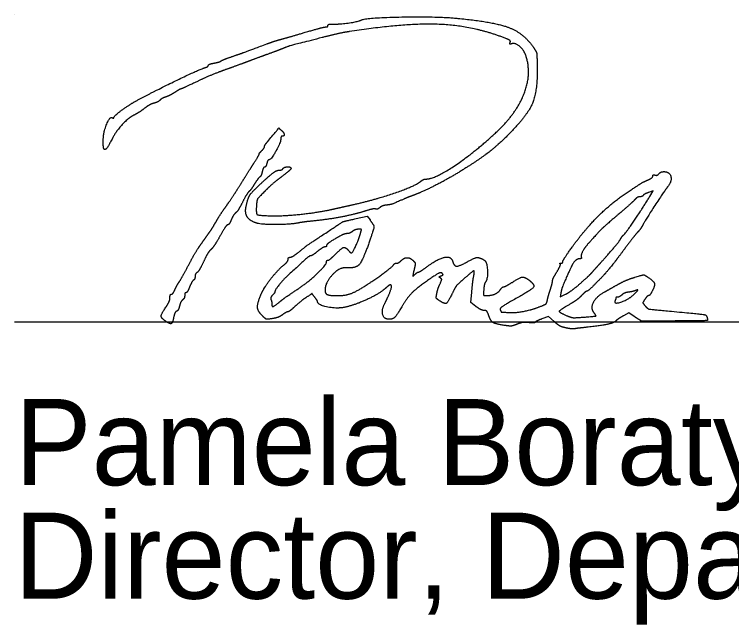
# Model space of a CAD drawing. Extents: x 0 to 34, y 0 to 22.
# Drawn here: x 24.528 to 25.693, y 4.24 to 5.232 of the extents above; entities that cross this region are included whole.
import ezdxf

# ---------------------------------------------------------------- set-up
doc = ezdxf.new("R2010")
doc.units = 0
for name, color, linetype in [('SH_Data', 7, 'Continuous'), ('SH_Text', 7, 'Continuous'), ('TX_P_1', 7, 'Continuous')]:
    doc.layers.add(name, color=color, linetype=linetype)

msp = doc.modelspace()

# ---------------------------------------------------------------- linework, layer by layer
at = {"layer": 'SH_Data'}
for p, q in [((24.5279, 5.2323), (24.5279, 5.2323)), ((24.5279, 4.7323), (28.0279, 4.7323))]:
    msp.add_line(p, q, dxfattribs=at)
at = {"layer": 'TX_P_1'}
for points in [[(25.5604, 4.9363), (25.5658, 4.9453), (25.5584, 4.9427)], [(25.0831, 4.9002), (25.1011, 4.9042), (25.1058, 4.898)], [(25.278, 4.7574), (25.2697, 4.7637), (25.2712, 4.7808)], [(25.416, 4.7793), (25.415, 4.7729), (25.4236, 4.7773)], [(25.5368, 4.74), (25.5262, 4.7468), (25.5178, 4.7423)], [(25.405, 4.733), (25.3958, 4.7413), (25.3852, 4.7372)]]:
    msp.add_lwpolyline(points, dxfattribs=at)
for points in [[(25.0465, 5.2165), (25.0561, 5.2162), (25.0871, 5.2206), (25.0905, 5.2227)], [(25.0905, 5.2227), (25.0973, 5.2269), (25.2143, 5.2292), (25.2487, 5.2258)], [(25.2487, 5.2258), (25.3079, 5.22), (25.3555, 5.2017), (25.3713, 5.1787)], [(25.0007, 5.2031), (25.0168, 5.2079), (25.0317, 5.2118), (25.0337, 5.2118)], [(25.0337, 5.2118), (25.0358, 5.2118), (25.0375, 5.2129), (25.0375, 5.2143)], [(25.0375, 5.2143), (25.0375, 5.2157), (25.0415, 5.2167), (25.0465, 5.2165)], [(25.3212, 5.1951), (25.2706, 5.2141), (25.1626, 5.2181), (25.0723, 5.2043)], [(24.9619, 5.192), (24.9672, 5.1934), (24.9846, 5.1984), (25.0007, 5.2031)], [(25.0723, 5.2043), (25.063, 5.2029), (25.0431, 5.1985), (25.0279, 5.1946)], [(24.9379, 5.1842), (24.9458, 5.1871), (24.9566, 5.1906), (24.9619, 5.192)], [(25.0279, 5.1946), (24.9769, 5.1814), (24.9726, 5.1802), (24.9619, 5.1758)], [(25.3335, 5.1865), (25.3345, 5.189), (25.331, 5.1914), (25.3212, 5.1951)], [(24.8815, 5.1636), (24.8962, 5.1687), (24.9027, 5.171), (24.9379, 5.1842)], [(24.9619, 5.1758), (24.9592, 5.1747), (24.949, 5.1709), (24.9391, 5.1673)], [(25.3359, 5.1844), (25.3333, 5.1834), (25.3326, 5.184), (25.3335, 5.1865)], [(25.3593, 5.1645), (25.356, 5.1742), (25.3416, 5.1866), (25.3359, 5.1844)], [(25.3713, 5.1787), (25.3762, 5.1714), (25.3771, 5.1671), (25.3775, 5.1492)], [(24.8635, 5.1564), (24.8648, 5.1574), (24.8729, 5.1606), (24.8815, 5.1636)], [(24.9391, 5.1673), (24.9292, 5.1637), (24.9141, 5.1582), (24.9055, 5.1549)], [(25.3138, 5.0433), (25.3447, 5.0727), (25.3686, 5.1362), (25.3593, 5.1645)], [(24.8431, 5.1493), (24.8431, 5.1504), (24.8471, 5.152), (24.8521, 5.153)], [(24.8521, 5.153), (24.857, 5.1539), (24.8622, 5.1554), (24.8635, 5.1564)], [(24.9055, 5.1549), (24.8969, 5.1517), (24.8807, 5.1458), (24.8695, 5.1418)], [(24.7255, 5.0914), (24.7557, 5.1077), (24.8293, 5.1433), (24.8377, 5.1457)], [(24.8695, 5.1418), (24.8583, 5.1378), (24.8379, 5.1293), (24.8243, 5.1228)], [(24.8377, 5.1457), (24.8407, 5.1466), (24.8431, 5.1482), (24.8431, 5.1493)], [(25.3775, 5.1492), (25.3782, 5.1084), (25.3621, 5.0687), (25.3327, 5.0388)], [(24.8243, 5.1228), (24.8106, 5.1163), (24.799, 5.111), (24.7984, 5.111)], [(24.7884, 5.1054), (24.7835, 5.1022), (24.7768, 5.0989), (24.7736, 5.0978)], [(24.7984, 5.111), (24.7978, 5.111), (24.7934, 5.1085), (24.7884, 5.1054)], [(24.7736, 5.0978), (24.7704, 5.0968), (24.7662, 5.0945), (24.7644, 5.0927)], [(24.6895, 5.0648), (24.6895, 5.0669), (24.7149, 5.0857), (24.7255, 5.0914)], [(24.7547, 5.0879), (24.7512, 5.087), (24.7445, 5.0834), (24.7399, 5.0798)], [(24.7644, 5.0927), (24.7626, 5.0909), (24.7583, 5.0887), (24.7547, 5.0879)], [(24.7399, 5.0798), (24.7353, 5.0762), (24.7281, 5.0715), (24.724, 5.0694)], [(24.6723, 5.0269), (24.6724, 5.0401), (24.683, 5.0667), (24.6872, 5.0641)], [(24.6872, 5.0641), (24.6885, 5.0634), (24.6895, 5.0637), (24.6895, 5.0648)], [(24.724, 5.0694), (24.7136, 5.0641), (24.6937, 5.0432), (24.6875, 5.0311)], [(24.9397, 5.0258), (24.9582, 5.048), (24.9575, 5.0474), (24.9616, 5.044)], [(24.9616, 5.044), (24.9659, 5.0405), (24.9668, 5.0342), (24.9631, 5.0342)], [(25.1971, 4.9646), (25.2112, 4.9646), (25.2793, 5.0105), (25.3138, 5.0433)], [(25.3327, 5.0388), (25.3141, 5.0199), (25.2817, 4.995), (25.2512, 4.9762)], [(24.6737, 5.0132), (24.6729, 5.014), (24.6723, 5.0202), (24.6723, 5.0269)], [(24.6875, 5.0311), (24.6808, 5.0182), (24.6755, 5.0114), (24.6737, 5.0132)], [(24.9343, 5.0172), (24.9343, 5.0184), (24.9367, 5.0223), (24.9397, 5.0258)], [(24.9607, 5.0291), (24.9607, 5.0236), (24.9448, 4.9958), (24.9416, 4.9958)], [(24.9631, 5.0342), (24.9618, 5.0342), (24.9607, 5.0319), (24.9607, 5.0291)], [(24.9295, 5.0102), (24.9321, 5.0128), (24.9343, 5.016), (24.9343, 5.0172)], [(24.9167, 4.9897), (24.9223, 4.9984), (24.9263, 5.0054), (24.9257, 5.0054)], [(24.9257, 5.0054), (24.9252, 5.0054), (24.9268, 5.0076), (24.9295, 5.0102)], [(24.8947, 4.9547), (24.9013, 4.9654), (24.9112, 4.9811), (24.9167, 4.9897)], [(24.9381, 4.9898), (24.9373, 4.9865), (24.9356, 4.9838), (24.9344, 4.9838)], [(24.9416, 4.9958), (24.9405, 4.9958), (24.9389, 4.9931), (24.9381, 4.9898)], [(24.9259, 4.9548), (24.9416, 4.9695), (24.9543, 4.979), (24.9583, 4.979)], [(24.9344, 4.9838), (24.9332, 4.9838), (24.9316, 4.9806), (24.9307, 4.9766)], [(24.9583, 4.979), (24.9608, 4.979), (24.9635, 4.9801), (24.9643, 4.9814)], [(24.9775, 4.9818), (24.9775, 4.9807), (24.9707, 4.9748), (24.9625, 4.9686)], [(24.9643, 4.9814), (24.9661, 4.9843), (24.9775, 4.9846), (24.9775, 4.9818)], [(24.9268, 4.968), (24.9255, 4.9672), (24.9217, 4.9621), (24.9183, 4.9566)], [(24.9307, 4.9766), (24.9298, 4.9727), (24.9281, 4.9688), (24.9268, 4.968)], [(24.9625, 4.9686), (24.9542, 4.9625), (24.9417, 4.9517), (24.9347, 4.9445)], [(25.2512, 4.9762), (25.232, 4.9644), (25.1908, 4.9434), (25.1767, 4.9383)], [(25.5577, 4.9632), (25.562, 4.9652), (25.5655, 4.968), (25.5655, 4.9695)], [(25.5655, 4.9695), (25.5655, 4.9711), (25.567, 4.9717), (25.5689, 4.971)], [(25.5689, 4.971), (25.5708, 4.9703), (25.5736, 4.9712), (25.5752, 4.9731)], [(25.5752, 4.9731), (25.5768, 4.975), (25.5805, 4.9766), (25.5834, 4.9766)], [(25.5834, 4.9766), (25.5928, 4.9766), (25.5966, 4.9606), (25.5892, 4.9516)], [(24.8729, 4.9218), (24.8783, 4.9293), (24.8881, 4.9441), (24.8947, 4.9547)], [(24.9045, 4.9202), (24.9073, 4.9333), (24.9134, 4.9432), (24.9259, 4.9548)], [(24.9183, 4.9566), (24.9149, 4.9511), (24.9108, 4.9455), (24.9091, 4.9442)], [(25.0771, 4.9227), (25.114, 4.9309), (25.1803, 4.9538), (25.1889, 4.9613)], [(25.1889, 4.9613), (25.191, 4.9631), (25.1946, 4.9646), (25.1971, 4.9646)], [(25.5287, 4.9462), (25.5476, 4.9585), (25.5495, 4.9596), (25.5577, 4.9632)], [(24.9091, 4.9442), (24.9075, 4.9428), (24.9028, 4.9352), (24.8988, 4.9272)], [(24.9347, 4.9445), (24.924, 4.9336), (24.9218, 4.9299), (24.9213, 4.9217)], [(25.4341, 4.8537), (25.4563, 4.8845), (25.5014, 4.9285), (25.5287, 4.9462)], [(25.5892, 4.9516), (25.585, 4.9466), (25.5522, 4.8961), (25.549, 4.8899)], [(25.5584, 4.9427), (25.5544, 4.9413), (25.5505, 4.9392), (25.5497, 4.938)], [(25.161, 4.9321), (25.144, 4.9246), (25.1391, 4.9229), (25.1325, 4.9222)], [(25.1767, 4.9383), (25.1721, 4.9366), (25.165, 4.9338), (25.161, 4.9321)], [(25.5356, 4.9304), (25.5329, 4.9274), (25.5204, 4.9164), (25.5079, 4.9058)], [(25.5176, 4.8734), (25.5204, 4.8754), (25.5486, 4.9169), (25.5604, 4.9363)], [(25.5444, 4.9358), (25.5422, 4.9358), (25.5382, 4.9334), (25.5356, 4.9304)], [(25.5497, 4.938), (25.549, 4.9368), (25.5466, 4.9358), (25.5444, 4.9358)], [(24.8562, 4.8962), (24.86, 4.9028), (24.8676, 4.9143), (24.8729, 4.9218)], [(24.8988, 4.9272), (24.8948, 4.9192), (24.8897, 4.9112), (24.8875, 4.9095)], [(24.9199, 4.8934), (24.9094, 4.8973), (24.9023, 4.9097), (24.9045, 4.9202)], [(24.9213, 4.9217), (24.9204, 4.9082), (24.9245, 4.9053), (24.9451, 4.9048)], [(25.0435, 4.9152), (25.0514, 4.917), (25.0665, 4.9203), (25.0771, 4.9227)], [(25.1325, 4.9222), (25.1286, 4.9217), (25.1237, 4.9199), (25.1217, 4.9181)], [(24.8875, 4.9095), (24.8854, 4.9077), (24.8821, 4.9026), (24.8803, 4.8982)], [(24.9451, 4.9048), (24.9643, 4.9043), (25.0222, 4.9104), (25.0435, 4.9152)], [(25.0969, 4.9122), (25.0804, 4.9069), (25.0353, 4.8984), (25.0115, 4.8961)], [(25.1149, 4.9159), (25.1132, 4.9165), (25.1051, 4.9148), (25.0969, 4.9122)], [(25.1217, 4.9181), (25.1196, 4.9163), (25.1165, 4.9153), (25.1149, 4.9159)], [(24.8432, 4.8756), (24.8465, 4.8803), (24.8524, 4.8896), (24.8562, 4.8962)], [(24.8803, 4.8982), (24.8784, 4.8938), (24.8759, 4.8902), (24.8746, 4.8902)], [(25.0115, 4.8961), (25.0032, 4.8953), (24.994, 4.8941), (24.9911, 4.8935)], [(25.0291, 4.8737), (25.0607, 4.8948), (25.0621, 4.8955), (25.0831, 4.9002)], [(25.1058, 4.898), (25.1124, 4.8893), (25.1122, 4.8844), (25.1045, 4.8619)], [(25.5079, 4.9058), (25.4883, 4.8893), (25.4766, 4.8779), (25.4599, 4.859)], [(24.8746, 4.8902), (24.8733, 4.8902), (24.8679, 4.8823), (24.8625, 4.8726)], [(24.9911, 4.8935), (24.9774, 4.8905), (24.9279, 4.8904), (24.9199, 4.8934)], [(25.549, 4.8899), (25.5473, 4.8865), (25.5434, 4.881), (25.5404, 4.8778)], [(24.8296, 4.8564), (24.8337, 4.8622), (24.8398, 4.8708), (24.8432, 4.8756)], [(24.8625, 4.8726), (24.8572, 4.863), (24.8505, 4.853), (24.8477, 4.8504)], [(24.9899, 4.8458), (25.0036, 4.8569), (25.0016, 4.8555), (25.0291, 4.8737)], [(25.0588, 4.8727), (25.0443, 4.8647), (25.0351, 4.8583), (25.0351, 4.8564)], [(25.0685, 4.8758), (25.0663, 4.8758), (25.0619, 4.8744), (25.0588, 4.8727)], [(25.0772, 4.8793), (25.0747, 4.8774), (25.0707, 4.8758), (25.0685, 4.8758)], [(25.0757, 4.8446), (25.0775, 4.8446), (25.0873, 4.8657), (25.0904, 4.8764)], [(25.0871, 4.8829), (25.0842, 4.8829), (25.0798, 4.8813), (25.0772, 4.8793)], [(25.0904, 4.8764), (25.0921, 4.8822), (25.0917, 4.883), (25.0871, 4.8829)], [(25.5137, 4.8683), (25.5149, 4.8704), (25.5167, 4.8727), (25.5176, 4.8734)], [(25.5404, 4.8778), (25.5374, 4.8746), (25.5285, 4.8632), (25.5206, 4.8526)], [(25.1045, 4.8619), (25.0942, 4.832), (25.0822, 4.8189), (25.0663, 4.8202)], [(25.4824, 4.8304), (25.4977, 4.8476), (25.5113, 4.8639), (25.5137, 4.8683)], [(24.8107, 4.8242), (24.817, 4.8361), (24.8255, 4.8506), (24.8296, 4.8564)], [(24.8477, 4.8504), (24.8448, 4.8479), (24.8393, 4.8388), (24.8354, 4.8302)], [(25.0324, 4.8542), (25.031, 4.8542), (25.0257, 4.851), (25.0207, 4.847)], [(25.0351, 4.8564), (25.0351, 4.8552), (25.0339, 4.8542), (25.0324, 4.8542)], [(25.0495, 4.8422), (25.0596, 4.8523), (25.0661, 4.8542), (25.0711, 4.8482)], [(25.4191, 4.8304), (25.4191, 4.8318), (25.4258, 4.8423), (25.4341, 4.8537)], [(25.4599, 4.859), (25.454, 4.8524), (25.4478, 4.8396), (25.4492, 4.8372)], [(25.5206, 4.8526), (25.5127, 4.8419), (25.505, 4.8317), (25.5036, 4.8299)], [(24.9727, 4.834), (24.9727, 4.8359), (24.9742, 4.8374), (24.9761, 4.8374)], [(25.0095, 4.8398), (25.0076, 4.8398), (24.9992, 4.8325), (24.9739, 4.8093)], [(24.9761, 4.8374), (24.9779, 4.8374), (24.9841, 4.8412), (24.9899, 4.8458)], [(25.0207, 4.847), (25.0157, 4.843), (25.0107, 4.8398), (25.0095, 4.8398)], [(25.0375, 4.8326), (25.0388, 4.8326), (25.0442, 4.8369), (25.0495, 4.8422)], [(25.0711, 4.8482), (25.0727, 4.8462), (25.0748, 4.8446), (25.0757, 4.8446)], [(25.1942, 4.8191), (25.2145, 4.8343), (25.2372, 4.8399), (25.2402, 4.8305)], [(25.264, 4.8301), (25.2759, 4.8367), (25.2832, 4.8374), (25.2914, 4.8328)], [(25.4492, 4.8372), (25.45, 4.836), (25.4489, 4.835), (25.4469, 4.835)], [(24.8354, 4.8302), (24.8314, 4.8216), (24.8267, 4.8137), (24.8249, 4.8127)], [(24.9292, 4.7779), (24.9337, 4.7884), (24.9569, 4.8178), (24.9673, 4.8262)], [(24.9673, 4.8262), (24.9702, 4.8286), (24.9727, 4.8321), (24.9727, 4.834)], [(24.989, 4.786), (25.0046, 4.7964), (25.0351, 4.8252), (25.0351, 4.8295)], [(25.0351, 4.8295), (25.0351, 4.8312), (25.0362, 4.8326), (25.0375, 4.8326)], [(25.1438, 4.8247), (25.1449, 4.8264), (25.1472, 4.8278), (25.149, 4.8278)], [(25.149, 4.8278), (25.1509, 4.8278), (25.1541, 4.8296), (25.1562, 4.8317)], [(25.1562, 4.8317), (25.1612, 4.8367), (25.1712, 4.8367), (25.1761, 4.8318)], [(25.1761, 4.8318), (25.1793, 4.8286), (25.1795, 4.8261), (25.1774, 4.817)], [(25.2402, 4.8305), (25.2426, 4.8229), (25.2507, 4.8228), (25.264, 4.8301)], [(25.2914, 4.8328), (25.2958, 4.8304), (25.2974, 4.8024), (25.2936, 4.7972)], [(25.4093, 4.8135), (25.4132, 4.8198), (25.4157, 4.8256), (25.4149, 4.8264)], [(25.4149, 4.8264), (25.4141, 4.8272), (25.4147, 4.8278), (25.4163, 4.8278)], [(25.4163, 4.8278), (25.4178, 4.8278), (25.4191, 4.829), (25.4191, 4.8304)], [(25.4469, 4.835), (25.4406, 4.835), (25.4311, 4.8198), (25.419, 4.7906)], [(25.4668, 4.813), (25.4699, 4.8165), (25.4769, 4.8244), (25.4824, 4.8304)], [(25.5036, 4.8299), (25.4903, 4.8135), (25.4857, 4.8083), (25.4739, 4.7962)], [(24.7953, 4.7966), (24.7975, 4.7999), (24.8044, 4.8123), (24.8107, 4.8242)], [(25.0663, 4.8202), (25.0559, 4.8211), (25.0327, 4.7957), (25.0327, 4.7835)], [(25.1011, 4.7929), (25.1197, 4.8053), (25.1421, 4.822), (25.1438, 4.8247)], [(25.1774, 4.817), (25.1751, 4.8067), (25.1752, 4.8063), (25.179, 4.8097)], [(25.1848, 4.8134), (25.1858, 4.8134), (25.19, 4.816), (25.1942, 4.8191)], [(25.2741, 4.8056), (25.2759, 4.815), (25.2733, 4.8155), (25.264, 4.8073)], [(24.8215, 4.8062), (24.8215, 4.8037), (24.8204, 4.801), (24.819, 4.8001)], [(24.8249, 4.8127), (24.823, 4.8116), (24.8215, 4.8087), (24.8215, 4.8062)], [(24.9739, 4.8093), (24.9648, 4.8009), (24.9511, 4.7838), (24.9511, 4.7809)], [(25.179, 4.8097), (25.1812, 4.8117), (25.1839, 4.8134), (25.1848, 4.8134)], [(25.2229, 4.8113), (25.2211, 4.8131), (25.2152, 4.8104), (25.2027, 4.8019)], [(25.2201, 4.8037), (25.2179, 4.8051), (25.2182, 4.806), (25.2213, 4.8071)], [(25.2194, 4.7938), (25.2222, 4.8001), (25.2224, 4.8023), (25.2201, 4.8037)], [(25.2213, 4.8071), (25.2243, 4.8083), (25.2247, 4.8095), (25.2229, 4.8113)], [(25.264, 4.8073), (25.2481, 4.7932), (25.2444, 4.7888), (25.2389, 4.7775)], [(25.2712, 4.7808), (25.272, 4.7901), (25.2733, 4.8013), (25.2741, 4.8056)], [(25.3367, 4.7966), (25.3496, 4.8048), (25.3572, 4.8056), (25.3649, 4.7996)], [(25.4023, 4.7987), (25.4023, 4.8006), (25.4054, 4.8072), (25.4093, 4.8135)], [(25.4467, 4.7941), (25.4546, 4.801), (25.4636, 4.8094), (25.4668, 4.813)], [(25.5067, 4.7922), (25.5146, 4.7967), (25.5278, 4.8024), (25.536, 4.8048)], [(25.536, 4.8048), (25.55, 4.8091), (25.5512, 4.8091), (25.5571, 4.8052)], [(25.5571, 4.8052), (25.5667, 4.7989), (25.5691, 4.7915), (25.5645, 4.7825)], [(24.7884, 4.784), (24.79, 4.7876), (24.7931, 4.7933), (24.7953, 4.7966)], [(24.819, 4.8001), (24.8176, 4.7993), (24.8148, 4.7944), (24.8127, 4.7892)], [(25.0526, 4.775), (25.0657, 4.775), (25.0848, 4.7821), (25.1011, 4.7929)], [(25.1407, 4.7897), (25.1407, 4.7928), (25.1367, 4.7923), (25.1331, 4.7888)], [(25.2027, 4.8019), (25.183, 4.7884), (25.1658, 4.7714), (25.1575, 4.757)], [(25.2143, 4.7782), (25.2151, 4.7824), (25.2173, 4.7894), (25.2194, 4.7938)], [(25.2936, 4.7972), (25.2923, 4.7955), (25.291, 4.7899), (25.2906, 4.7846)], [(25.3231, 4.7894), (25.3243, 4.7894), (25.3304, 4.7926), (25.3367, 4.7966)], [(25.3649, 4.7996), (25.3746, 4.792), (25.3677, 4.784), (25.3361, 4.7663)], [(25.3988, 4.7846), (25.4007, 4.7905), (25.4023, 4.7969), (25.4023, 4.7987)], [(25.419, 4.7906), (25.4179, 4.788), (25.4166, 4.7829), (25.416, 4.7793)], [(25.4236, 4.7773), (25.4284, 4.7797), (25.4388, 4.7873), (25.4467, 4.7941)], [(25.4739, 4.7962), (25.4664, 4.7885), (25.4593, 4.7822), (25.4583, 4.7822)], [(25.4871, 4.7811), (25.49, 4.7827), (25.4988, 4.7876), (25.5067, 4.7922)], [(24.7831, 4.7774), (24.7845, 4.7774), (24.7869, 4.7804), (24.7884, 4.784)], [(24.8068, 4.7798), (24.8056, 4.7798), (24.8047, 4.7778), (24.8047, 4.7753)], [(24.8127, 4.7892), (24.8107, 4.784), (24.808, 4.7798), (24.8068, 4.7798)], [(24.9511, 4.7809), (24.9511, 4.7801), (24.9494, 4.7778), (24.9473, 4.7757)], [(24.9575, 4.7637), (24.965, 4.7698), (24.9703, 4.7735), (24.989, 4.786)], [(25.0327, 4.7835), (25.0327, 4.7783), (25.0405, 4.775), (25.0526, 4.775)], [(25.1331, 4.7888), (25.1235, 4.7796), (25.0847, 4.7608), (25.0663, 4.7564)], [(25.1301, 4.763), (25.1342, 4.7707), (25.1407, 4.787), (25.1407, 4.7897)], [(25.2906, 4.7846), (25.2901, 4.777), (25.2908, 4.775), (25.2939, 4.775)], [(25.2939, 4.775), (25.3023, 4.775), (25.3143, 4.7798), (25.3175, 4.7845)], [(25.3175, 4.7845), (25.3194, 4.7872), (25.3219, 4.7894), (25.3231, 4.7894)], [(25.394, 4.7675), (25.3947, 4.771), (25.3968, 4.7787), (25.3988, 4.7846)], [(25.4583, 4.7822), (25.4572, 4.7822), (25.4533, 4.7791), (25.4497, 4.7752)], [(25.4701, 4.7467), (25.464, 4.7542), (25.4738, 4.7739), (25.4871, 4.7811)], [(25.5261, 4.7807), (25.5222, 4.7802), (25.5173, 4.7782), (25.5151, 4.7762)], [(25.5379, 4.7835), (25.5352, 4.7825), (25.5299, 4.7812), (25.5261, 4.7807)], [(25.5355, 4.7779), (25.541, 4.7835), (25.5415, 4.7848), (25.5379, 4.7835)], [(25.5645, 4.7825), (25.5623, 4.7784), (25.5596, 4.775), (25.5585, 4.775)], [(24.7749, 4.7575), (24.7781, 4.7622), (24.7807, 4.7686), (24.7807, 4.7717)], [(24.7807, 4.7717), (24.7807, 4.7749), (24.7818, 4.7774), (24.7831, 4.7774)], [(24.8012, 4.7679), (24.7993, 4.7664), (24.7971, 4.7618), (24.7962, 4.7579)], [(24.8047, 4.7753), (24.8047, 4.7728), (24.8031, 4.7695), (24.8012, 4.7679)], [(24.9309, 4.7422), (24.9232, 4.7498), (24.9226, 4.7627), (24.9292, 4.7779)], [(24.9473, 4.7757), (24.9453, 4.7737), (24.9442, 4.7704), (24.9449, 4.7685)], [(24.9449, 4.7685), (24.9457, 4.7666), (24.9463, 4.7635), (24.9463, 4.7616)], [(25.0048, 4.7738), (24.9966, 4.7684), (24.994, 4.7664), (24.9828, 4.7564)], [(25.0161, 4.7724), (25.0116, 4.7783), (25.0115, 4.7783), (25.0048, 4.7738)], [(25.0206, 4.7651), (25.0206, 4.7659), (25.0186, 4.7692), (25.0161, 4.7724)], [(25.2189, 4.7667), (25.2139, 4.7699), (25.2131, 4.7719), (25.2143, 4.7782)], [(25.2389, 4.7775), (25.2322, 4.7638), (25.2274, 4.7611), (25.2189, 4.7667)], [(25.3813, 4.7569), (25.3901, 4.7603), (25.3931, 4.7627), (25.394, 4.7675)], [(25.4497, 4.7752), (25.4461, 4.7714), (25.438, 4.7653), (25.4317, 4.7617)], [(25.504, 4.7669), (25.5015, 4.7603), (25.527, 4.7693), (25.5355, 4.7779)], [(25.5055, 4.7716), (25.5055, 4.771), (25.5048, 4.7689), (25.504, 4.7669)], [(25.5083, 4.7726), (25.5067, 4.7726), (25.5055, 4.7722), (25.5055, 4.7716)], [(25.5151, 4.7762), (25.5129, 4.7742), (25.5098, 4.7726), (25.5083, 4.7726)], [(25.5526, 4.7692), (25.5491, 4.7638), (25.5491, 4.763), (25.553, 4.7582)], [(25.5585, 4.775), (25.5574, 4.775), (25.5547, 4.7724), (25.5526, 4.7692)], [(24.7732, 4.7338), (24.7662, 4.7387), (24.7667, 4.7454), (24.7749, 4.7575)], [(24.7962, 4.7579), (24.7953, 4.7539), (24.7932, 4.7501), (24.7915, 4.7495)], [(24.9463, 4.7616), (24.9463, 4.7568), (24.9497, 4.7574), (24.9575, 4.7637)], [(24.9828, 4.7564), (24.978, 4.7521), (24.9732, 4.7486), (24.9721, 4.7486)], [(25.0663, 4.7564), (25.0534, 4.7533), (25.0208, 4.7595), (25.0206, 4.7651)], [(25.1368, 4.7366), (25.1284, 4.7366), (25.1244, 4.7524), (25.1301, 4.763)], [(25.1575, 4.757), (25.1493, 4.7429), (25.1429, 4.7366), (25.1368, 4.7366)], [(25.291, 4.751), (25.2884, 4.751), (25.2826, 4.7539), (25.278, 4.7574)], [(25.3361, 4.7663), (25.3229, 4.7589), (25.3167, 4.7541), (25.3175, 4.7519)], [(25.3315, 4.7476), (25.342, 4.747), (25.3682, 4.7518), (25.3813, 4.7569)], [(25.4317, 4.7617), (25.4138, 4.7512), (25.4127, 4.748), (25.4257, 4.7424)], [(25.553, 4.7582), (25.5566, 4.7537), (25.5616, 4.7527), (25.5955, 4.7496)], [(24.7915, 4.7495), (24.7898, 4.7488), (24.7877, 4.7447), (24.7869, 4.7403)], [(24.9636, 4.7439), (24.96, 4.7413), (24.9526, 4.7384), (24.9471, 4.7376)], [(24.9721, 4.7486), (24.971, 4.7486), (24.9672, 4.7465), (24.9636, 4.7439)], [(25.2985, 4.7432), (25.2967, 4.7484), (25.2941, 4.751), (25.291, 4.751)], [(25.3175, 4.7519), (25.3188, 4.7485), (25.3195, 4.7483), (25.3315, 4.7476)], [(25.4525, 4.74), (25.472, 4.7415), (25.4738, 4.7422), (25.4701, 4.7467)], [(25.5955, 4.7496), (25.6446, 4.745), (25.6528, 4.7435), (25.6538, 4.7387)], [(24.7869, 4.7403), (24.785, 4.7305), (24.7808, 4.7285), (24.7732, 4.7338)], [(24.9471, 4.7376), (24.9384, 4.7363), (24.9362, 4.7369), (24.9309, 4.7422)], [(25.3239, 4.7267), (25.3089, 4.7291), (25.302, 4.7335), (25.2985, 4.7432)], [(25.3852, 4.7372), (25.3794, 4.735), (25.3744, 4.7324), (25.374, 4.7315)], [(25.4196, 4.7236), (25.4166, 4.7242), (25.41, 4.7285), (25.405, 4.733)], [(25.4257, 4.7424), (25.4325, 4.7395), (25.439, 4.7389), (25.4525, 4.74)], [(25.5061, 4.7345), (25.5024, 4.7307), (25.4809, 4.7259), (25.4575, 4.7235)], [(25.5178, 4.7423), (25.5132, 4.7398), (25.5079, 4.7363), (25.5061, 4.7345)], [(25.5835, 4.7336), (25.5478, 4.7332), (25.5474, 4.7333), (25.5368, 4.74)], [(25.6538, 4.7387), (25.6546, 4.7345), (25.6526, 4.7343), (25.5835, 4.7336)], [(25.345, 4.7286), (25.338, 4.7258), (25.3325, 4.7253), (25.3239, 4.7267)], [(25.3639, 4.7312), (25.3581, 4.7319), (25.3508, 4.7309), (25.345, 4.7286)], [(25.374, 4.7315), (25.3736, 4.7306), (25.369, 4.7305), (25.3639, 4.7312)], [(25.4299, 4.7214), (25.4272, 4.7219), (25.4226, 4.7229), (25.4196, 4.7236)], [(25.4383, 4.7211), (25.4363, 4.7207), (25.4325, 4.7209), (25.4299, 4.7214)], [(25.4575, 4.7235), (25.4489, 4.7226), (25.4403, 4.7215), (25.4383, 4.7211)]]:
    msp.add_open_spline(points, degree=2, dxfattribs=at)

# ---------------------------------------------------------------- texts
at = {"layer": 'SH_Text'}
for s, p in [('Pamela Boratyn', (24.5286, 4.4669)), ('Director, Department of Transportation', (24.5279, 4.2823))]:
    msp.add_text(s, height=0.14, dxfattribs=at).set_placement(p)

doc.saveas('drawing.dxf')
